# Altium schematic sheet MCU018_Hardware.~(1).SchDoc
size 431 x 279 mm; Date: Not shown in title block; ApprovedBy: Not shown in title block; CheckedBy: Not shown in title block; Author: Not shown in title block; CompanyName: Not shown in title block; Engineer: Not shown in title block; Organization: Not shown in title block; Address1: Not shown in title block; Address2: Not shown in title block; Address3: Not shown in title block; Address4: Not shown in title block; DocumentNumber: 6; Revision: Use project parameter SCH_Rev; SheetNumber: 6; SheetTotal: 6; PageSetup: Record=PageOptions¦CenterHorizontal=True¦CenterVertical=True¦PrintScale=1.00¦XCorrection=1.00¦YCorrection=1.00¦PrintKind=0¦BorderSize=5000000¦LeftOffset=0¦BottomOffset=0¦Orientation=2¦PaperLength=1000¦PaperWidth=1000¦Scale=100¦PaperSource=15¦PrintQuality=600¦MediaType=1¦DitherType=10¦PaperKind=Letter¦PrintScaleMode=1
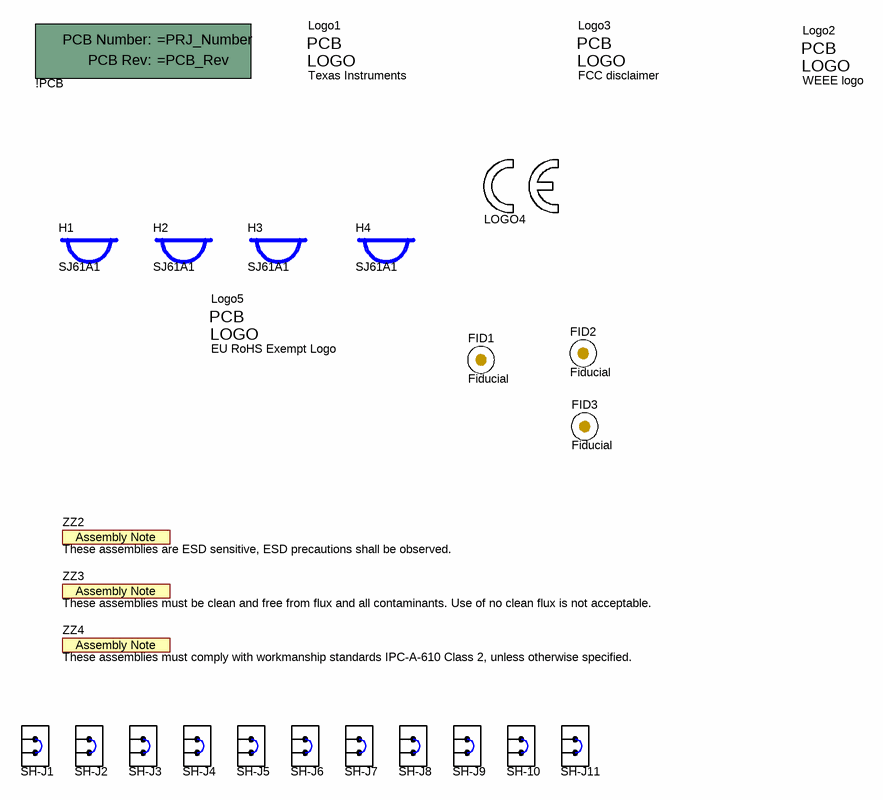
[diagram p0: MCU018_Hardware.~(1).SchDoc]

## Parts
!PCB  Printed Circuit Board  (value not drawn)  (mechanical)
FID1  Fiducial  [Fiducial10-30]
FID2  Fiducial  [Fiducial10-30]
FID3  Fiducial  [Fiducial10-30]
H1  SJ61A1  [Bumpon_SJ61A1]
H2  SJ61A1  [Bumpon_SJ61A1]
H3  SJ61A1  [Bumpon_SJ61A1]
H4  SJ61A1  [Bumpon_SJ61A1]
Logo1  Texas Instruments  [TI_Stacked_Overlay_Small]  (no BOM)
Logo2  WEEE logo  [WEEE_Minimum]  (no BOM)
Logo3  FCC disclaimer  [FCC_disclaimer]  (no BOM)
LOGO4  CE Mark  [CE_Mark_5mm]  (value not drawn)  (no BOM)
Logo5  EU RoHS Exempt Logo  [EURoHS_Exempt_60mil]  (no BOM)
SH-10  60900213421  [Wurth_60900213421]  (value not drawn)
SH-J1  60900213421  [Wurth_60900213421]  (value not drawn)
SH-J2  60900213421  [Wurth_60900213421]  (value not drawn)
SH-J3  60900213421  [Wurth_60900213421]  (value not drawn)
SH-J4  60900213421  [Wurth_60900213421]  (value not drawn)
SH-J5  60900213421  [Wurth_60900213421]  (value not drawn)
SH-J6  60900213421  [Wurth_60900213421]  (value not drawn)
SH-J7  60900213421  [Wurth_60900213421]  (value not drawn)
SH-J8  60900213421  [Wurth_60900213421]  (value not drawn)
SH-J9  60900213421  [Wurth_60900213421]  (value not drawn)
SH-J11  60900213421  [Wurth_60900213421]  (value not drawn)
ZZ2  These assemblies are ESD sensitive, ESD precautions shall be observed.  [AssemblyNote]  (no BOM)
ZZ3  These assemblies must be clean and free from flux and all contaminants. Use of no clean flux is not acceptable.  [AssemblyNote]  (no BOM)
ZZ4  These assemblies must comply with workmanship standards IPC-A-610 Class 2, unless otherwise specified.  [AssemblyNote]  (no BOM)

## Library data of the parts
!PCB = PCB: Manufacturer: Any; SymbolCreator: a0412235
FID1-FID3 = CMP-0077181-1: Fiducial mark.  There is nothing to buy or mount.
H1-H4 = SJ61A1: Bumpon, Cylindrical, 0.312 X 0.200, Black; Manufacturer: 3M; SymbolCreator: a0412235; Green_Lifecycle: Not Set; Green_REACh: Incomplete
Logo1 = TI_Logo: Texas Instrument Corporate Signature; SymbolCreator: codlsc
Logo2 = CMP-0074769-1
Logo3 = FCC_disclaimer: SymbolCreator: codlsc
LOGO4 = CE Mark: SymbolCreator: a0412235
Logo5 = CMP-0074848-1: Lib Reference: EURoHS_Exempt; SymbolCreator: a0412235
SH-10 SH-J1-SH-J9 SH-J11 = 60900213421: Shunt, 2.54mm, Gold, Black; Manufacturer: Wurth Elektronik
ZZ2-ZZ4 = AssemblyNote: SymbolCreator: codlsc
